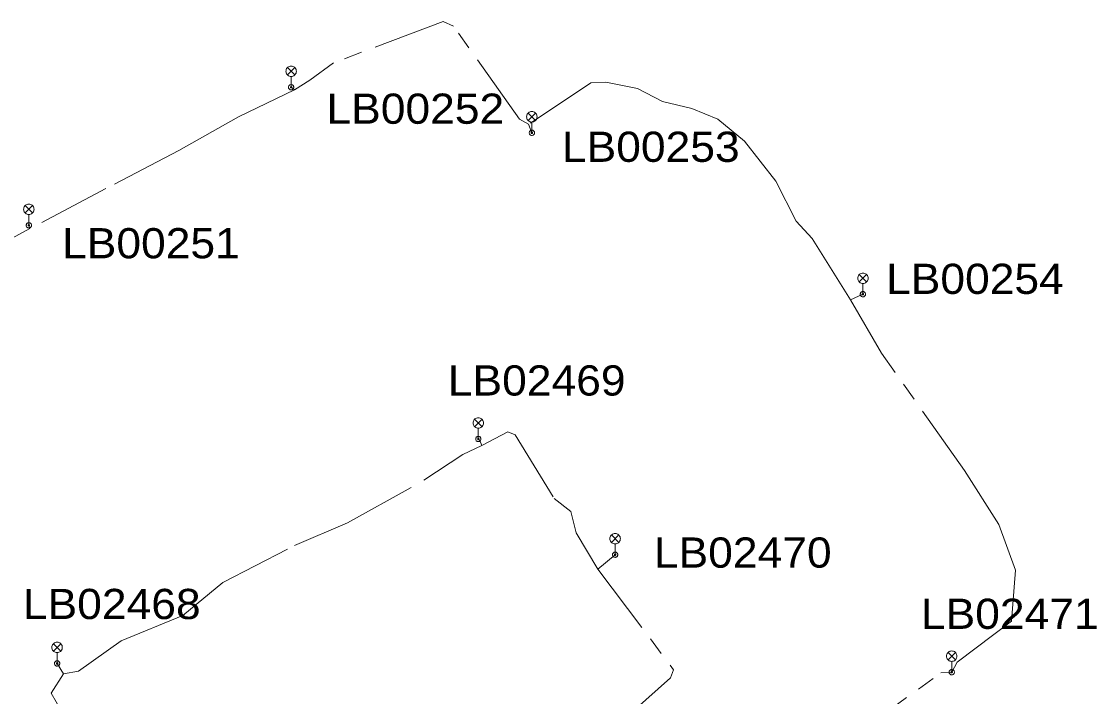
# Model space of a CAD drawing. Extents: x -688049 to -687261, y -973611 to -973038.
# Drawn here: x -687766.3 to -687689.1, y -973427.5 to -973379.1 of the extents above; entities that cross this region are included whole.
import ezdxf

# ---------------------------------------------------------------- set-up
doc = ezdxf.new("R2010")
doc.units = 0
doc.header["$LTSCALE"] = 0.87
doc.linetypes.add('LONG_DASH_SHORT_DASH', pattern=[9.9, 6, -1.2, 1.5, -1.2])
doc.layers.add('1', color=7, linetype='Continuous', lineweight=13)

msp = doc.modelspace()

# ---------------------------------------------------------------- linework, layer by layer
at = {"layer": '1'}
for p, q in [((-687747.225, -973382.355), (-687746.695, -973382.885)), ((-687747.225, -973382.885), (-687746.695, -973382.355)), ((-687746.96, -973383.77), (-687746.96, -973382.995)), ((-687729.935, -973385.625), (-687729.405, -973386.155)), ((-687729.935, -973386.155), (-687729.405, -973385.625)), ((-687729.67, -973387.04), (-687729.67, -973386.265)), ((-687766.065, -973392.265), (-687765.535, -973392.795)), ((-687766.065, -973392.795), (-687765.535, -973392.265)), ((-687765.8, -973393.68), (-687765.8, -973392.905)), ((-687706.155, -973397.215), (-687705.625, -973397.745)), ((-687706.155, -973397.745), (-687705.625, -973397.215)), ((-687705.89, -973398.63), (-687705.89, -973397.855)), ((-687733.78, -973407.606), (-687733.25, -973408.136)), ((-687733.78, -973408.136), (-687733.25, -973407.606)), ((-687733.515, -973409.021), (-687733.515, -973408.246)), ((-687723.954, -973415.911), (-687723.424, -973416.441)), ((-687723.954, -973416.441), (-687723.424, -973415.911)), ((-687723.689, -973417.326), (-687723.689, -973416.551)), ((-687764.035, -973423.715), (-687763.505, -973424.245)), ((-687764.035, -973424.245), (-687763.505, -973423.715)), ((-687763.77, -973425.13), (-687763.77, -973424.355)), ((-687699.775, -973424.345), (-687699.245, -973424.875)), ((-687699.775, -973424.875), (-687699.245, -973424.345)), ((-687699.51, -973425.76), (-687699.51, -973424.985))]:
    msp.add_line(p, q, dxfattribs=at)
at = {"layer": '1', "linetype": 'LONG_DASH_SHORT_DASH'}
for p, q in [((-687746.73, -973383.95), (-687746.96, -973383.77)), ((-687765.8, -973393.68), (-687765.73, -973393.92)), ((-687706.79, -973399.04), (-687705.89, -973398.63)), ((-687733.27, -973409.49), (-687733.42, -973409.09)), ((-687724.92, -973418.37), (-687723.69, -973417.33)), ((-687763.77, -973425.13), (-687763.32, -973425.88))]:
    msp.add_line(p, q, dxfattribs=at)
for points in [[(-687729.9, -973386.43), (-687730.56, -973386.06), (-687735.3, -973379.38), (-687736.04, -973379.05), (-687743.91, -973382.02), (-687745.62, -973383.26), (-687746.73, -973383.95)], [(-687706.79, -973399.04), (-687709.53, -973394.63), (-687710.69, -973393.39), (-687712.15, -973390.52), (-687714.4, -973387.65), (-687716.31, -973386.05), (-687718.17, -973385.3), (-687720.29, -973384.8), (-687722.07, -973383.87), (-687724.35, -973383.4), (-687725.43, -973383.46), (-687729.9, -973386.43), (-687729.67, -973387.04)], [(-687746.73, -973383.95), (-687750.73, -973385.89), (-687755.02, -973388.31), (-687760.26, -973391.04), (-687765.73, -973393.92)], [(-687765.73, -973393.92), (-687769.8, -973396.11), (-687776.17, -973399.38), (-687781.96, -973402.21), (-687791.77, -973406.93), (-687796.56, -973409.01), (-687798.09, -973410.16), (-687798.98, -973412.4), (-687799.94, -973415.52), (-687800.22, -973417.08), (-687800.01, -973418.09)], [(-687699.51, -973425.76), (-687699.13, -973425.03), (-687695.22, -973422.09), (-687694.94, -973418.44), (-687696.12, -973415.15), (-687698.59, -973411.27), (-687704.56, -973402.85), (-687706.79, -973399.04)], [(-687733.27, -973409.49), (-687731.39, -973408.5), (-687730.86, -973408.71), (-687728.06, -973413.28), (-687726.88, -973414.23), (-687726.48, -973415.76), (-687724.92, -973418.37)], [(-687763.32, -973425.88), (-687762.23, -973425.68), (-687759.16, -973423.52), (-687754.74, -973421.68), (-687751.86, -973419.32), (-687746.73, -973416.66), (-687742.9, -973415.03), (-687737.42, -973411.98), (-687734.62, -973410.14), (-687733.27, -973409.49)], [(-687724.92, -973418.37), (-687719.49, -973425.59), (-687719.72, -973426.17), (-687722.38, -973428.53)], [(-687758.5, -973437.37), (-687760.56, -973434.47), (-687760.07, -973432.69), (-687760.35, -973430.88), (-687761.31, -973429.72), (-687763.11, -973429.13), (-687764.19, -973427.27), (-687763.32, -973425.88)], [(-687706.89, -973433.2), (-687707.18, -973431.82), (-687706.97, -973430.66), (-687700.3, -973425.8), (-687699.51, -973425.76)]]:
    msp.add_lwpolyline(points, dxfattribs=at)
at = {"layer": '1'}
for points in [[(-687746.585, -973382.62), (-687746.591, -973382.555), (-687746.608, -973382.492), (-687746.635, -973382.432), (-687746.673, -973382.379), (-687746.719, -973382.333), (-687746.772, -973382.295), (-687746.832, -973382.268), (-687746.895, -973382.251), (-687746.96, -973382.245), (-687747.025, -973382.251), (-687747.088, -973382.268), (-687747.148, -973382.295), (-687747.201, -973382.333), (-687747.247, -973382.379), (-687747.285, -973382.432), (-687747.312, -973382.492), (-687747.329, -973382.555), (-687747.335, -973382.62), (-687747.329, -973382.685), (-687747.312, -973382.748), (-687747.285, -973382.808), (-687747.247, -973382.861), (-687747.201, -973382.907), (-687747.148, -973382.945), (-687747.088, -973382.972), (-687747.025, -973382.989), (-687746.96, -973382.995), (-687746.895, -973382.989), (-687746.832, -973382.972), (-687746.772, -973382.945), (-687746.719, -973382.907), (-687746.673, -973382.861), (-687746.635, -973382.808), (-687746.608, -973382.748), (-687746.591, -973382.685)], [(-687746.77, -973383.77), (-687746.773, -973383.737), (-687746.781, -973383.705), (-687746.795, -973383.675), (-687746.814, -973383.648), (-687746.838, -973383.624), (-687746.865, -973383.605), (-687746.895, -973383.591), (-687746.927, -973383.583), (-687746.96, -973383.58), (-687746.993, -973383.583), (-687747.025, -973383.591), (-687747.055, -973383.605), (-687747.082, -973383.624), (-687747.106, -973383.648), (-687747.125, -973383.675), (-687747.139, -973383.705), (-687747.147, -973383.737), (-687747.15, -973383.77), (-687747.147, -973383.803), (-687747.139, -973383.835), (-687747.125, -973383.865), (-687747.106, -973383.892), (-687747.082, -973383.916), (-687747.055, -973383.935), (-687747.025, -973383.949), (-687746.993, -973383.957), (-687746.96, -973383.96), (-687746.927, -973383.957), (-687746.895, -973383.949), (-687746.865, -973383.935), (-687746.838, -973383.916), (-687746.814, -973383.892), (-687746.795, -973383.865), (-687746.781, -973383.835), (-687746.773, -973383.803)], [(-687746.91, -973383.77), (-687746.911, -973383.761), (-687746.913, -973383.753), (-687746.917, -973383.745), (-687746.922, -973383.738), (-687746.928, -973383.732), (-687746.935, -973383.727), (-687746.943, -973383.723), (-687746.951, -973383.721), (-687746.96, -973383.72), (-687746.969, -973383.721), (-687746.977, -973383.723), (-687746.985, -973383.727), (-687746.992, -973383.732), (-687746.998, -973383.738), (-687747.003, -973383.745), (-687747.007, -973383.753), (-687747.009, -973383.761), (-687747.01, -973383.77), (-687747.009, -973383.779), (-687747.007, -973383.787), (-687747.003, -973383.795), (-687746.998, -973383.802), (-687746.992, -973383.808), (-687746.985, -973383.813), (-687746.977, -973383.817), (-687746.969, -973383.819), (-687746.96, -973383.82), (-687746.951, -973383.819), (-687746.943, -973383.817), (-687746.935, -973383.813), (-687746.928, -973383.808), (-687746.922, -973383.802), (-687746.917, -973383.795), (-687746.913, -973383.787), (-687746.911, -973383.779)], [(-687729.295, -973385.89), (-687729.301, -973385.825), (-687729.318, -973385.762), (-687729.345, -973385.702), (-687729.383, -973385.649), (-687729.429, -973385.603), (-687729.482, -973385.565), (-687729.542, -973385.538), (-687729.605, -973385.521), (-687729.67, -973385.515), (-687729.735, -973385.521), (-687729.798, -973385.538), (-687729.858, -973385.565), (-687729.911, -973385.603), (-687729.957, -973385.649), (-687729.995, -973385.702), (-687730.022, -973385.762), (-687730.039, -973385.825), (-687730.045, -973385.89), (-687730.039, -973385.955), (-687730.022, -973386.018), (-687729.995, -973386.078), (-687729.957, -973386.131), (-687729.911, -973386.177), (-687729.858, -973386.215), (-687729.798, -973386.242), (-687729.735, -973386.259), (-687729.67, -973386.265), (-687729.605, -973386.259), (-687729.542, -973386.242), (-687729.482, -973386.215), (-687729.429, -973386.177), (-687729.383, -973386.131), (-687729.345, -973386.078), (-687729.318, -973386.018), (-687729.301, -973385.955)], [(-687729.48, -973387.04), (-687729.483, -973387.007), (-687729.491, -973386.975), (-687729.505, -973386.945), (-687729.524, -973386.918), (-687729.548, -973386.894), (-687729.575, -973386.875), (-687729.605, -973386.861), (-687729.637, -973386.853), (-687729.67, -973386.85), (-687729.703, -973386.853), (-687729.735, -973386.861), (-687729.765, -973386.875), (-687729.792, -973386.894), (-687729.816, -973386.918), (-687729.835, -973386.945), (-687729.849, -973386.975), (-687729.857, -973387.007), (-687729.86, -973387.04), (-687729.857, -973387.073), (-687729.849, -973387.105), (-687729.835, -973387.135), (-687729.816, -973387.162), (-687729.792, -973387.186), (-687729.765, -973387.205), (-687729.735, -973387.219), (-687729.703, -973387.227), (-687729.67, -973387.23), (-687729.637, -973387.227), (-687729.605, -973387.219), (-687729.575, -973387.205), (-687729.548, -973387.186), (-687729.524, -973387.162), (-687729.505, -973387.135), (-687729.491, -973387.105), (-687729.483, -973387.073)], [(-687729.62, -973387.04), (-687729.621, -973387.031), (-687729.623, -973387.023), (-687729.627, -973387.015), (-687729.632, -973387.008), (-687729.638, -973387.002), (-687729.645, -973386.997), (-687729.653, -973386.993), (-687729.661, -973386.991), (-687729.67, -973386.99), (-687729.679, -973386.991), (-687729.687, -973386.993), (-687729.695, -973386.997), (-687729.702, -973387.002), (-687729.708, -973387.008), (-687729.713, -973387.015), (-687729.717, -973387.023), (-687729.719, -973387.031), (-687729.72, -973387.04), (-687729.719, -973387.049), (-687729.717, -973387.057), (-687729.713, -973387.065), (-687729.708, -973387.072), (-687729.702, -973387.078), (-687729.695, -973387.083), (-687729.687, -973387.087), (-687729.679, -973387.089), (-687729.67, -973387.09), (-687729.661, -973387.089), (-687729.653, -973387.087), (-687729.645, -973387.083), (-687729.638, -973387.078), (-687729.632, -973387.072), (-687729.627, -973387.065), (-687729.623, -973387.057), (-687729.621, -973387.049)], [(-687765.425, -973392.53), (-687765.431, -973392.465), (-687765.448, -973392.402), (-687765.475, -973392.342), (-687765.513, -973392.289), (-687765.559, -973392.243), (-687765.612, -973392.205), (-687765.672, -973392.178), (-687765.735, -973392.161), (-687765.8, -973392.155), (-687765.865, -973392.161), (-687765.928, -973392.178), (-687765.988, -973392.205), (-687766.041, -973392.243), (-687766.087, -973392.289), (-687766.125, -973392.342), (-687766.152, -973392.402), (-687766.169, -973392.465), (-687766.175, -973392.53), (-687766.169, -973392.595), (-687766.152, -973392.658), (-687766.125, -973392.718), (-687766.087, -973392.771), (-687766.041, -973392.817), (-687765.988, -973392.855), (-687765.928, -973392.882), (-687765.865, -973392.899), (-687765.8, -973392.905), (-687765.735, -973392.899), (-687765.672, -973392.882), (-687765.612, -973392.855), (-687765.559, -973392.817), (-687765.513, -973392.771), (-687765.475, -973392.718), (-687765.448, -973392.658), (-687765.431, -973392.595)], [(-687765.61, -973393.68), (-687765.613, -973393.647), (-687765.621, -973393.615), (-687765.635, -973393.585), (-687765.654, -973393.558), (-687765.678, -973393.534), (-687765.705, -973393.515), (-687765.735, -973393.501), (-687765.767, -973393.493), (-687765.8, -973393.49), (-687765.833, -973393.493), (-687765.865, -973393.501), (-687765.895, -973393.515), (-687765.922, -973393.534), (-687765.946, -973393.558), (-687765.965, -973393.585), (-687765.979, -973393.615), (-687765.987, -973393.647), (-687765.99, -973393.68), (-687765.987, -973393.713), (-687765.979, -973393.745), (-687765.965, -973393.775), (-687765.946, -973393.802), (-687765.922, -973393.826), (-687765.895, -973393.845), (-687765.865, -973393.859), (-687765.833, -973393.867), (-687765.8, -973393.87), (-687765.767, -973393.867), (-687765.735, -973393.859), (-687765.705, -973393.845), (-687765.678, -973393.826), (-687765.654, -973393.802), (-687765.635, -973393.775), (-687765.621, -973393.745), (-687765.613, -973393.713)], [(-687765.75, -973393.68), (-687765.751, -973393.671), (-687765.753, -973393.663), (-687765.757, -973393.655), (-687765.762, -973393.648), (-687765.768, -973393.642), (-687765.775, -973393.637), (-687765.783, -973393.633), (-687765.791, -973393.631), (-687765.8, -973393.63), (-687765.809, -973393.631), (-687765.817, -973393.633), (-687765.825, -973393.637), (-687765.832, -973393.642), (-687765.838, -973393.648), (-687765.843, -973393.655), (-687765.847, -973393.663), (-687765.849, -973393.671), (-687765.85, -973393.68), (-687765.849, -973393.689), (-687765.847, -973393.697), (-687765.843, -973393.705), (-687765.838, -973393.712), (-687765.832, -973393.718), (-687765.825, -973393.723), (-687765.817, -973393.727), (-687765.809, -973393.729), (-687765.8, -973393.73), (-687765.791, -973393.729), (-687765.783, -973393.727), (-687765.775, -973393.723), (-687765.768, -973393.718), (-687765.762, -973393.712), (-687765.757, -973393.705), (-687765.753, -973393.697), (-687765.751, -973393.689)], [(-687705.515, -973397.48), (-687705.521, -973397.415), (-687705.538, -973397.352), (-687705.565, -973397.293), (-687705.603, -973397.239), (-687705.649, -973397.193), (-687705.702, -973397.155), (-687705.762, -973397.128), (-687705.825, -973397.111), (-687705.89, -973397.105), (-687705.955, -973397.111), (-687706.018, -973397.128), (-687706.078, -973397.155), (-687706.131, -973397.193), (-687706.177, -973397.239), (-687706.215, -973397.293), (-687706.242, -973397.352), (-687706.259, -973397.415), (-687706.265, -973397.48), (-687706.259, -973397.545), (-687706.242, -973397.608), (-687706.215, -973397.668), (-687706.177, -973397.721), (-687706.131, -973397.767), (-687706.078, -973397.805), (-687706.018, -973397.832), (-687705.955, -973397.849), (-687705.89, -973397.855), (-687705.825, -973397.849), (-687705.762, -973397.832), (-687705.702, -973397.805), (-687705.649, -973397.767), (-687705.603, -973397.721), (-687705.565, -973397.668), (-687705.538, -973397.608), (-687705.521, -973397.545)], [(-687705.7, -973398.63), (-687705.703, -973398.597), (-687705.711, -973398.565), (-687705.725, -973398.535), (-687705.744, -973398.508), (-687705.768, -973398.484), (-687705.795, -973398.465), (-687705.825, -973398.451), (-687705.857, -973398.443), (-687705.89, -973398.44), (-687705.923, -973398.443), (-687705.955, -973398.451), (-687705.985, -973398.465), (-687706.012, -973398.484), (-687706.036, -973398.508), (-687706.055, -973398.535), (-687706.069, -973398.565), (-687706.077, -973398.597), (-687706.08, -973398.63), (-687706.077, -973398.663), (-687706.069, -973398.695), (-687706.055, -973398.725), (-687706.036, -973398.752), (-687706.012, -973398.776), (-687705.985, -973398.795), (-687705.955, -973398.809), (-687705.923, -973398.817), (-687705.89, -973398.82), (-687705.857, -973398.817), (-687705.825, -973398.809), (-687705.795, -973398.795), (-687705.768, -973398.776), (-687705.744, -973398.752), (-687705.725, -973398.725), (-687705.711, -973398.695), (-687705.703, -973398.663)], [(-687705.84, -973398.63), (-687705.841, -973398.621), (-687705.843, -973398.613), (-687705.847, -973398.605), (-687705.852, -973398.598), (-687705.858, -973398.592), (-687705.865, -973398.587), (-687705.873, -973398.583), (-687705.881, -973398.581), (-687705.89, -973398.58), (-687705.899, -973398.581), (-687705.907, -973398.583), (-687705.915, -973398.587), (-687705.922, -973398.592), (-687705.928, -973398.598), (-687705.933, -973398.605), (-687705.937, -973398.613), (-687705.939, -973398.621), (-687705.94, -973398.63), (-687705.939, -973398.639), (-687705.937, -973398.647), (-687705.933, -973398.655), (-687705.928, -973398.662), (-687705.922, -973398.668), (-687705.915, -973398.673), (-687705.907, -973398.677), (-687705.899, -973398.679), (-687705.89, -973398.68), (-687705.881, -973398.679), (-687705.873, -973398.677), (-687705.865, -973398.673), (-687705.858, -973398.668), (-687705.852, -973398.662), (-687705.847, -973398.655), (-687705.843, -973398.647), (-687705.841, -973398.639)], [(-687733.14, -973407.871), (-687733.146, -973407.806), (-687733.163, -973407.743), (-687733.19, -973407.684), (-687733.228, -973407.63), (-687733.274, -973407.584), (-687733.328, -973407.546), (-687733.387, -973407.519), (-687733.45, -973407.502), (-687733.515, -973407.496), (-687733.58, -973407.502), (-687733.643, -973407.519), (-687733.702, -973407.546), (-687733.756, -973407.584), (-687733.802, -973407.63), (-687733.84, -973407.684), (-687733.867, -973407.743), (-687733.884, -973407.806), (-687733.89, -973407.871), (-687733.884, -973407.936), (-687733.867, -973407.999), (-687733.84, -973408.058), (-687733.802, -973408.112), (-687733.756, -973408.158), (-687733.702, -973408.196), (-687733.643, -973408.223), (-687733.58, -973408.24), (-687733.515, -973408.246), (-687733.45, -973408.24), (-687733.387, -973408.223), (-687733.328, -973408.196), (-687733.274, -973408.158), (-687733.228, -973408.112), (-687733.19, -973408.058), (-687733.163, -973407.999), (-687733.146, -973407.936)], [(-687733.325, -973409.021), (-687733.328, -973408.988), (-687733.336, -973408.956), (-687733.35, -973408.926), (-687733.369, -973408.899), (-687733.393, -973408.875), (-687733.42, -973408.856), (-687733.45, -973408.842), (-687733.482, -973408.834), (-687733.515, -973408.831), (-687733.548, -973408.834), (-687733.58, -973408.842), (-687733.61, -973408.856), (-687733.637, -973408.875), (-687733.661, -973408.899), (-687733.68, -973408.926), (-687733.694, -973408.956), (-687733.702, -973408.988), (-687733.705, -973409.021), (-687733.702, -973409.054), (-687733.694, -973409.086), (-687733.68, -973409.116), (-687733.661, -973409.143), (-687733.637, -973409.167), (-687733.61, -973409.186), (-687733.58, -973409.2), (-687733.548, -973409.208), (-687733.515, -973409.211), (-687733.482, -973409.208), (-687733.45, -973409.2), (-687733.42, -973409.186), (-687733.393, -973409.167), (-687733.369, -973409.143), (-687733.35, -973409.116), (-687733.336, -973409.086), (-687733.328, -973409.054)], [(-687733.465, -973409.021), (-687733.466, -973409.012), (-687733.468, -973409.004), (-687733.472, -973408.996), (-687733.477, -973408.989), (-687733.483, -973408.983), (-687733.49, -973408.978), (-687733.498, -973408.974), (-687733.506, -973408.972), (-687733.515, -973408.971), (-687733.524, -973408.972), (-687733.532, -973408.974), (-687733.54, -973408.978), (-687733.547, -973408.983), (-687733.553, -973408.989), (-687733.558, -973408.996), (-687733.562, -973409.004), (-687733.564, -973409.012), (-687733.565, -973409.021), (-687733.564, -973409.03), (-687733.562, -973409.038), (-687733.558, -973409.046), (-687733.553, -973409.053), (-687733.547, -973409.059), (-687733.54, -973409.064), (-687733.532, -973409.068), (-687733.524, -973409.07), (-687733.515, -973409.071), (-687733.506, -973409.07), (-687733.498, -973409.068), (-687733.49, -973409.064), (-687733.483, -973409.059), (-687733.477, -973409.053), (-687733.472, -973409.046), (-687733.468, -973409.038), (-687733.466, -973409.03)], [(-687723.314, -973416.176), (-687723.32, -973416.111), (-687723.337, -973416.048), (-687723.364, -973415.989), (-687723.402, -973415.935), (-687723.448, -973415.889), (-687723.502, -973415.851), (-687723.561, -973415.824), (-687723.624, -973415.807), (-687723.689, -973415.801), (-687723.754, -973415.807), (-687723.817, -973415.824), (-687723.876, -973415.851), (-687723.93, -973415.889), (-687723.976, -973415.935), (-687724.014, -973415.989), (-687724.041, -973416.048), (-687724.058, -973416.111), (-687724.064, -973416.176), (-687724.058, -973416.241), (-687724.041, -973416.304), (-687724.014, -973416.364), (-687723.976, -973416.417), (-687723.93, -973416.463), (-687723.876, -973416.501), (-687723.817, -973416.528), (-687723.754, -973416.545), (-687723.689, -973416.551), (-687723.624, -973416.545), (-687723.561, -973416.528), (-687723.502, -973416.501), (-687723.448, -973416.463), (-687723.402, -973416.417), (-687723.364, -973416.364), (-687723.337, -973416.304), (-687723.32, -973416.241)], [(-687723.499, -973417.326), (-687723.502, -973417.293), (-687723.51, -973417.261), (-687723.524, -973417.231), (-687723.543, -973417.204), (-687723.567, -973417.18), (-687723.594, -973417.161), (-687723.624, -973417.147), (-687723.656, -973417.139), (-687723.689, -973417.136), (-687723.722, -973417.139), (-687723.754, -973417.147), (-687723.784, -973417.161), (-687723.811, -973417.18), (-687723.835, -973417.204), (-687723.854, -973417.231), (-687723.868, -973417.261), (-687723.876, -973417.293), (-687723.879, -973417.326), (-687723.876, -973417.359), (-687723.868, -973417.391), (-687723.854, -973417.421), (-687723.835, -973417.448), (-687723.811, -973417.472), (-687723.784, -973417.491), (-687723.754, -973417.505), (-687723.722, -973417.513), (-687723.689, -973417.516), (-687723.656, -973417.513), (-687723.624, -973417.505), (-687723.594, -973417.491), (-687723.567, -973417.472), (-687723.543, -973417.448), (-687723.524, -973417.421), (-687723.51, -973417.391), (-687723.502, -973417.359)], [(-687723.639, -973417.326), (-687723.64, -973417.317), (-687723.642, -973417.309), (-687723.646, -973417.301), (-687723.651, -973417.294), (-687723.657, -973417.288), (-687723.664, -973417.283), (-687723.672, -973417.279), (-687723.68, -973417.277), (-687723.689, -973417.276), (-687723.698, -973417.277), (-687723.706, -973417.279), (-687723.714, -973417.283), (-687723.721, -973417.288), (-687723.727, -973417.294), (-687723.732, -973417.301), (-687723.736, -973417.309), (-687723.738, -973417.317), (-687723.739, -973417.326), (-687723.738, -973417.335), (-687723.736, -973417.343), (-687723.732, -973417.351), (-687723.727, -973417.358), (-687723.721, -973417.364), (-687723.714, -973417.369), (-687723.706, -973417.373), (-687723.698, -973417.375), (-687723.689, -973417.376), (-687723.68, -973417.375), (-687723.672, -973417.373), (-687723.664, -973417.369), (-687723.657, -973417.364), (-687723.651, -973417.358), (-687723.646, -973417.351), (-687723.642, -973417.343), (-687723.64, -973417.335)], [(-687763.395, -973423.98), (-687763.401, -973423.915), (-687763.418, -973423.852), (-687763.445, -973423.793), (-687763.483, -973423.739), (-687763.529, -973423.693), (-687763.582, -973423.655), (-687763.642, -973423.628), (-687763.705, -973423.611), (-687763.77, -973423.605), (-687763.835, -973423.611), (-687763.898, -973423.628), (-687763.958, -973423.655), (-687764.011, -973423.693), (-687764.057, -973423.739), (-687764.095, -973423.793), (-687764.122, -973423.852), (-687764.139, -973423.915), (-687764.145, -973423.98), (-687764.139, -973424.045), (-687764.122, -973424.108), (-687764.095, -973424.168), (-687764.057, -973424.221), (-687764.011, -973424.267), (-687763.958, -973424.305), (-687763.898, -973424.332), (-687763.835, -973424.349), (-687763.77, -973424.355), (-687763.705, -973424.349), (-687763.642, -973424.332), (-687763.582, -973424.305), (-687763.529, -973424.267), (-687763.483, -973424.221), (-687763.445, -973424.168), (-687763.418, -973424.108), (-687763.401, -973424.045)], [(-687699.135, -973424.61), (-687699.141, -973424.545), (-687699.158, -973424.482), (-687699.185, -973424.423), (-687699.223, -973424.369), (-687699.269, -973424.323), (-687699.322, -973424.285), (-687699.382, -973424.258), (-687699.445, -973424.241), (-687699.51, -973424.235), (-687699.575, -973424.241), (-687699.638, -973424.258), (-687699.698, -973424.285), (-687699.751, -973424.323), (-687699.797, -973424.369), (-687699.835, -973424.423), (-687699.862, -973424.482), (-687699.879, -973424.545), (-687699.885, -973424.61), (-687699.879, -973424.675), (-687699.862, -973424.738), (-687699.835, -973424.798), (-687699.797, -973424.851), (-687699.751, -973424.897), (-687699.698, -973424.935), (-687699.638, -973424.962), (-687699.575, -973424.979), (-687699.51, -973424.985), (-687699.445, -973424.979), (-687699.382, -973424.962), (-687699.322, -973424.935), (-687699.269, -973424.897), (-687699.223, -973424.851), (-687699.185, -973424.798), (-687699.158, -973424.738), (-687699.141, -973424.675)], [(-687763.58, -973425.13), (-687763.583, -973425.097), (-687763.591, -973425.065), (-687763.605, -973425.035), (-687763.624, -973425.008), (-687763.648, -973424.984), (-687763.675, -973424.965), (-687763.705, -973424.951), (-687763.737, -973424.943), (-687763.77, -973424.94), (-687763.803, -973424.943), (-687763.835, -973424.951), (-687763.865, -973424.965), (-687763.892, -973424.984), (-687763.916, -973425.008), (-687763.935, -973425.035), (-687763.949, -973425.065), (-687763.957, -973425.097), (-687763.96, -973425.13), (-687763.957, -973425.163), (-687763.949, -973425.195), (-687763.935, -973425.225), (-687763.916, -973425.252), (-687763.892, -973425.276), (-687763.865, -973425.295), (-687763.835, -973425.309), (-687763.803, -973425.317), (-687763.77, -973425.32), (-687763.737, -973425.317), (-687763.705, -973425.309), (-687763.675, -973425.295), (-687763.648, -973425.276), (-687763.624, -973425.252), (-687763.605, -973425.225), (-687763.591, -973425.195), (-687763.583, -973425.163)], [(-687763.72, -973425.13), (-687763.721, -973425.121), (-687763.723, -973425.113), (-687763.727, -973425.105), (-687763.732, -973425.098), (-687763.738, -973425.092), (-687763.745, -973425.087), (-687763.753, -973425.083), (-687763.761, -973425.081), (-687763.77, -973425.08), (-687763.779, -973425.081), (-687763.787, -973425.083), (-687763.795, -973425.087), (-687763.802, -973425.092), (-687763.808, -973425.098), (-687763.813, -973425.105), (-687763.817, -973425.113), (-687763.819, -973425.121), (-687763.82, -973425.13), (-687763.819, -973425.139), (-687763.817, -973425.147), (-687763.813, -973425.155), (-687763.808, -973425.162), (-687763.802, -973425.168), (-687763.795, -973425.173), (-687763.787, -973425.177), (-687763.779, -973425.179), (-687763.77, -973425.18), (-687763.761, -973425.179), (-687763.753, -973425.177), (-687763.745, -973425.173), (-687763.738, -973425.168), (-687763.732, -973425.162), (-687763.727, -973425.155), (-687763.723, -973425.147), (-687763.721, -973425.139)], [(-687699.32, -973425.76), (-687699.323, -973425.727), (-687699.331, -973425.695), (-687699.345, -973425.665), (-687699.364, -973425.638), (-687699.388, -973425.614), (-687699.415, -973425.595), (-687699.445, -973425.581), (-687699.477, -973425.573), (-687699.51, -973425.57), (-687699.543, -973425.573), (-687699.575, -973425.581), (-687699.605, -973425.595), (-687699.632, -973425.614), (-687699.656, -973425.638), (-687699.675, -973425.665), (-687699.689, -973425.695), (-687699.697, -973425.727), (-687699.7, -973425.76), (-687699.697, -973425.793), (-687699.689, -973425.825), (-687699.675, -973425.855), (-687699.656, -973425.882), (-687699.632, -973425.906), (-687699.605, -973425.925), (-687699.575, -973425.939), (-687699.543, -973425.947), (-687699.51, -973425.95), (-687699.477, -973425.947), (-687699.445, -973425.939), (-687699.415, -973425.925), (-687699.388, -973425.906), (-687699.364, -973425.882), (-687699.345, -973425.855), (-687699.331, -973425.825), (-687699.323, -973425.793)], [(-687699.46, -973425.76), (-687699.461, -973425.751), (-687699.463, -973425.743), (-687699.467, -973425.735), (-687699.472, -973425.728), (-687699.478, -973425.722), (-687699.485, -973425.717), (-687699.493, -973425.713), (-687699.501, -973425.711), (-687699.51, -973425.71), (-687699.519, -973425.711), (-687699.527, -973425.713), (-687699.535, -973425.717), (-687699.542, -973425.722), (-687699.548, -973425.728), (-687699.553, -973425.735), (-687699.557, -973425.743), (-687699.559, -973425.751), (-687699.56, -973425.76), (-687699.559, -973425.769), (-687699.557, -973425.777), (-687699.553, -973425.785), (-687699.548, -973425.792), (-687699.542, -973425.798), (-687699.535, -973425.803), (-687699.527, -973425.807), (-687699.519, -973425.809), (-687699.51, -973425.81), (-687699.501, -973425.809), (-687699.493, -973425.807), (-687699.485, -973425.803), (-687699.478, -973425.798), (-687699.472, -973425.792), (-687699.467, -973425.785), (-687699.463, -973425.777), (-687699.461, -973425.769)]]:
    msp.add_lwpolyline(points, close=True, dxfattribs=at)

# ---------------------------------------------------------------- texts
at = {"layer": '1', "width": 1.1}
for s, height, p in [('LB00252', 2.167, (-687744.42, -973386.391)), ('LB00253', 2.167, (-687727.508, -973389.126)), ('LB00251', 2.167, (-687763.412, -973396.049)), ('LB00254', 2.167, (-687704.227, -973398.606)), ('LB02469', 2.168, (-687735.707, -973405.902)), ('LB02470', 2.168, (-687720.905, -973418.255)), ('LB02468', 2.168, (-687766.229, -973421.947)), ('LB02471', 2.168, (-687701.726, -973422.653))]:
    msp.add_text(s, height=height, dxfattribs=at).set_placement(p)

doc.saveas('drawing.dxf')
